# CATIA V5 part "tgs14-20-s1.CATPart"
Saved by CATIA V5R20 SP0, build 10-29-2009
Part number: TGS14-20-S1
Revision: 1
Definition: design
Nomenclature: TGS14-20-S1
Source: made
Description: NOT SPECIFIED
Bounding box of the stored display mesh (mm): x -22 to 0.8, y 0 to 14, z -6 to 6
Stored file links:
  C:\Users\Raffaele\Desktop\3D X SITO CF\I-MOLD\TGS-S1\tgs14-s1.step\tgs14-20-s1.CATPart
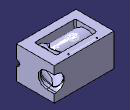
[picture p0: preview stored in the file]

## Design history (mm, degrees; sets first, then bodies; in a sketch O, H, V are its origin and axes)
Set1
  Line1 "LINE #4084": stored without definition
  DatumCurve1 "COMPOSITE_CURVE #4137"
  DatumCurve2 "COMPOSITE_CURVE #4188"
  DatumCurve3 "COMPOSITE_CURVE #4267"
  DatumCurve4 "COMPOSITE_CURVE #4310"
  DatumCurve5 "COMPOSITE_CURVE #4539"
  DatumCurve6 "COMPOSITE_CURVE #4680"
  DatumCurve7 "COMPOSITE_CURVE #4707"
  DatumCurve8 "COMPOSITE_CURVE #4765"
  DatumCurve9 "COMPOSITE_CURVE #4820"
  DatumCurve10 "COMPOSITE_CURVE #4849"
  DatumSurface1 "OPEN_SHELL #4074"
Body1 "MANIFOLD_SOLID_BREP #4075" (main body)
  Solid1: solid without history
